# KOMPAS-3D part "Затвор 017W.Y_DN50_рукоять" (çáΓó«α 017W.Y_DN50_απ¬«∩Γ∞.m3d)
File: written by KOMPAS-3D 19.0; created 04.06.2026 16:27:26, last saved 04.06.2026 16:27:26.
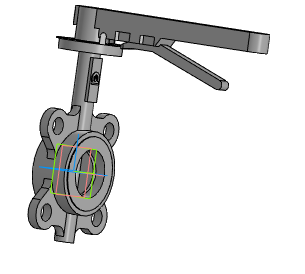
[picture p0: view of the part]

Document properties: Автор: Энергия; Полное имя файла: ..\..\..\3d для проектировщиков\017W разные\x.x Тип 017W.Y(S) Затвор дисковый поворотный межфланцевый\Затвор 017W.Y(S)_DN32-DN350_рукоять\Затвор 017W.Y_DN50_рукоять.a3d

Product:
- Part/product: Затвор 017W.Y_DN50_рукоять
    Масса: 3.68621

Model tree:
1. Операция без истории:1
